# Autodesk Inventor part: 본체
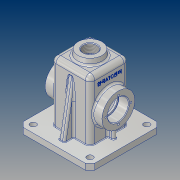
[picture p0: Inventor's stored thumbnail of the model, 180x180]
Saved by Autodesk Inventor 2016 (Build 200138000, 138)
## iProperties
Created: 2018-10
Part Number: 본체
Material: 알루미늄 6061
Document SubType Name: Modeling
Designer: user
Density: 2.7 g/cm^3
Appearance: 알루미늄 - 평지
Mass: 795.193 g
Surface Area: 895.751 cm^2
Volume: 294.516 cm^3
Author: user
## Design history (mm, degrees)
sketch "스케치1"
  geometry: L1 (52, -60)-(-52, -60); L2 (-60, -52)-(-60, 52); L3 (-52, 60)-(52, 60); L4 (60, 52)-(60, -52); L5 (60, -60)-(-60, 60); L6 (-60, -60)-(60, 60); L7 (-52, 60)-(-60, 52); L8 (-52, -60)-(-60, -52); L9 (60, -52)-(52, -60); L10 (60, 52)-(52, 60); 1 further point
  constraints: 20 end point, 8 point on line, 2 midpoint, 2 parallel, 1 horizontal, 1 perpendicular
  dimensions: "d0" = 120 distance of L5.end L6.end; "d1" = 120 distance of L6.end L5.start; "d2" = 8 distance of L3.start L5.end; "d3" = 8 distance of L2.end L5.end (= d2); "d4" = 8 distance of L1.end L6.start (= d2); "d5" = 8 distance of L2.start L6.start (= d4); "d6" = 8 distance of L4.end L5.start (= d2); "d7" = 8 distance of L1.start L5.start (= d6); "d8" = 8 distance of L4.start L6.end (= d2); "d9" = 8 distance of L3.end L6.end (= d8)
extrude "돌출1" new body sketch "스케치1" distance "d10" = 10; taper "d11" = 0 deg
sketch "스케치2"
  geometry: L1 (-32.5, -32.5)-(32.5, -32.5); L2 (32.5, -32.5)-(32.5, 32.5); L3 (32.5, 32.5)-(-32.5, 32.5); L4 (-32.5, 32.5)-(-32.5, -32.5); L5 (-32.5, -32.5)-(32.5, 32.5); L6 (32.5, -32.5)-(-32.5, 32.5); 1 further point
  constraints: 12 end point, 2 midpoint, 2 parallel, 1 horizontal, 1 perpendicular
  dimensions: "d12" = 65 distance of L3.end L2.end; "d13" = 65 distance of L2.end L1.end
extrude "돌출2" join sketch "스케치2" distance "d14" = 100; taper "d15" = 0 deg
sketch "스케치3"
  geometry: L1 (27.5, -27.5)-(-27.5, -27.5); L2 (-27.5, -27.5)-(-27.5, 27.5); L3 (-27.5, 27.5)-(27.5, 27.5); L4 (27.5, 27.5)-(27.5, -27.5); L5 (27.5, -27.5)-(-27.5, 27.5); L6 (-27.5, -27.5)-(27.5, 27.5); 1 further point
  constraints: 12 end point, 2 midpoint, 2 parallel, 1 horizontal, 1 perpendicular
  dimensions: "d16" = 55 distance of L2.end L3.end; "d17" = 55 distance of L1.end L2.end
extrude "돌출3" cut sketch "스케치3" distance "d18" = 105; taper "d19" = 0 deg
sketch "스케치4"
  geometry: L1 (-10, 84.5)-(-10, -19.5) reference; L2 (-10, -27.5)-(0, -27.5) reference; C1 r 27.5 at (45, 32.5); 1 further point
  constraints: 1 centre point
  dimensions: "d20" = 27.5 radius of C1; "d21" = 55 distance from line of L1 C1.centre; "d22" = 60 distance from line of L2 C1.centre
extrude "돌출4" join sketch "스케치4" distance "d23" = 15; taper "d24" = 0 deg
hole "구멍1" diameter "d27" = 35; stored, may be unused: countersink angle "d31" = 90 deg, drill point angle "d33" = 0 deg; dims "d28" = 6, "d29" = 4, "d30" = 2, "d32" = 17, "d55" = 10, "d56" = 10
hole "구멍2" diameter "d36" = 30; stored, may be unused: countersink angle "d40" = 90 deg, drill point angle "d42" = 0 deg; dims "d37" = 6, "d38" = 4, "d39" = 2, "d41" = 15, "d57" = 10, "d58" = 10
node "작업 평면1"
sketch "스케치6"
  geometry: C1 r 20 at (0, 0); 1 further point
  constraints: 1 centre point, 1 coincident
  dimensions: "d44" = 20 radius of C1
extrude "돌출5" join sketch "스케치6" distance "d45" = 10; taper "d46" = 7 deg
sketch "스케치8"
  geometry: 2 further points
  constraints: 1 coincident
hole "구멍3" sketch "스케치8" at (0, 0) diameter "d47" = 22.835; stored, may be unused: countersink angle "d51" = 90 deg, drill point angle "d53" = 0 deg; dims "d48" = 50, "d49" = 4, "d50" = 2, "d52" = 59.3
sketch "스케치9"
  geometry: C1 r 27.5 at (0, 0) reference; 2 further points
  constraints: 1 horizontal alignment
  dimensions: "d54" = 21 distance of C1.centre point (21, 0)
hole "구멍4" sketch "스케치9" at (21, 0) diameter "d59" = 3.242; stored, may be unused: countersink angle "d63" = 90 deg, drill point angle "d65" = 118 deg; dims "d60" = 8, "d61" = 4, "d62" = 2, "d64" = 10
sketch "스케치10"
  geometry: L1 (-32.5, 10)-(-32.5, 110) reference; L2 (-60, 0)-(-60, 10) reference; L3 (32.5, 10)-(32.5, 110) reference; L4 (60, 0)-(60, 10) reference; L5 (32.5, 97.905)-(48, 10); L6 (52, 10)-(-52, 10) reference; 1 further point
  constraints: 2 end point, 2 point on line
  dimensions: "d70" = 10 deg angle of L4 L5; "d71" = 12 distance of L4.end L5.end
extrude "돌출6" join sketch "스케치10" stored distance "d72" = 10; taper "d73" = 0 deg
sketch "스케치11"
  geometry: L1 (-52, 10)-(52, 10) reference; L2 (27.5, 0)-(27.5, 105) reference; L3 (27.5, 10)-(42.5, 10); L4 (42.5, 10)-(42.5, 29.937); L5 (42.5, 29.937)-(27.5, 29.937); L6 (27.5, 29.937)-(27.5, 10); 1 further point
  constraints: 8 end point, 2 parallel, 2 point on line, 1 horizontal, 1 perpendicular
  dimensions: "d74" = 15 distance between parallel lines of L2 L4; "d75" = 19.93714 distance between parallel lines of L1 L5
extrude "돌출7" join sketch "스케치11" stored distance "d76" = 6; taper "d77" = 0 deg
sketch "스케치12"
  geometry: L1 (-60, 52)-(-60, -52) reference; L2 (52, 60)-(-52, 60) reference; L3 (-47.5, 47.5)-(47.5, 47.5); L4 (-47.5, 47.5)-(-47.5, -47.5); L5 (-60, 0)-(-47.5, 0); L6 (0, 60)-(0, 47.5); C1 r 5 at (-47.5, 47.5); C2 r 5 at (47.5, 47.5); C3 r 5 at (47.5, -47.5); C4 r 5 at (-47.5, -47.5); 1 further point
  constraints: 8 end point, 4 centre point, 4 midpoint, 3 equal radius, 2 horizontal alignment, 2 perpendicular, 2 vertical alignment, 1 horizontal, 1 vertical
  dimensions: "d78" = 95 distance of L3.end L3.start; "d79" = 95 distance of L4.end L3.start; "d80" = 47.5 distance of L5.end L4.end; "d81" = 10 diameter of C1; "d82" = 47.5 distance of L3.start L6.end
hole "구멍5" sketch "스케치12" at (-47.5, 47.5), (47.5, 47.5), (47.5, -47.5), (-47.5, -47.5) diameter "d83" = 10; stored, may be unused: countersink angle "d87" = 90 deg, drill point angle "d89" = 0 deg; dims "d84" = 8, "d85" = 4, "d86" = 2, "d88" = 15
fillet "모깎기1" dims "d90" = 8
fillet "모깎기2" dims "d91" = 8
fillet "모깎기3" dims "d92" = 3
fillet "모깎기4" dims "d93" = 3
fillet "모깎기5" dims "d94" = 3
fillet "모깎기7" dims "d96" = 3
fillet "모깎기8" dims "d97" = 3
fillet "모깎기9" dims "d98" = 3
fillet "모깎기10" dims "d99" = 0.3
fillet "모깎기11" dims "d100" = 3
fillet "모깎기12" dims "d101" = 3
fillet "모깎기13" dims "d102" = 3
fillet "모깎기14" dims "d103" = 3
fillet "모깎기15" dims "d104" = 1
chamfer "모따기2" distance "d108" = 1; stored, may be unused: second distance "d109" = 2, angle "d110" = 45 deg
chamfer "모따기3" distance "d111" = 1; stored, may be unused: second distance "d112" = 2, angle "d113" = 45 deg
sketch "스케치13"
  geometry: L1 (0, -8)-(91, -8) reference; L2 (-18, 4.5)-(-18, 44.5) reference; 2 further points
  constraints: 1 other
  dimensions: "d114" = 32.5 distance from line of L1 point (8, 24.5); "d115" = 26 distance from line of point (8, 24.5) L2
feature "엠보싱1" sketch "스케치13" dims "d116" = 0.5, "d117" = 0
node "솔리드1"
mirror "대칭1"
pattern_circular "원형 패턴1" dims angle "d67" = 360 deg
mirror "대칭2"
mirror "대칭3"
mirror "대칭4"
